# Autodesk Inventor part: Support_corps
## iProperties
Shininess: 64.0
Length Units: 11269
Angle Units: 11279
Time Units: 11290
Mass Units: 11283
Length Display Precision: 3
Angle Display Precision: 2
Compacted: True
Part Number: Support_corps
Document SubType Name: Sheet Metal
Created: 2008-02
Material: Acier inoxydable, austénitique
Designer: Pascal
Density: 8.03 g/cm^3
Density: 0.0
Volumn: 0.0
Area: 0.0
PropertySet Name: Model Information
Control State: 0
Master: False
Checked Out: False
Author: Pascal
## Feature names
1. Plaque1
2. Pli1
3. Plaque2
4. Pli2
5. Plaque3
6. Pli3
7. Ouverture1
